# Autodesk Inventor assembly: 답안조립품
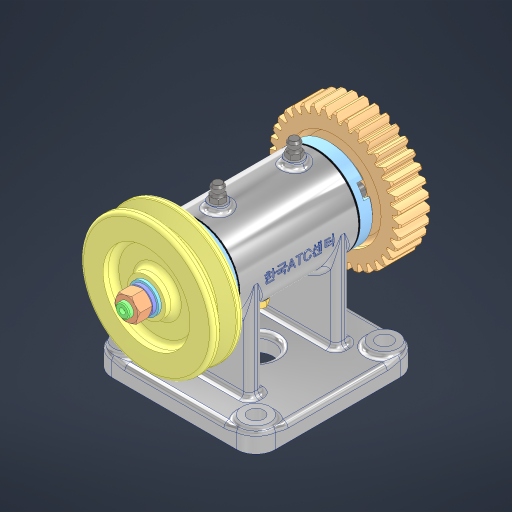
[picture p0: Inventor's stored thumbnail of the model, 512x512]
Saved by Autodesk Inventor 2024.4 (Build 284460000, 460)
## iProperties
Created: 2025-10
Part Number: 답안조립품
Document SubType Name: Assembly
Designer: user
Author: user
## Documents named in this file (24)
- C:\Users\user\Desktop\751003V1003\답안조립품.iam
- C:\Users\user\Desktop\751003V1003\본체.ipt
- C:\Users\user\Desktop\751003V1003\축\축\축.ipt
- C:\Users\user\Desktop\751003V1003\커버\커버\커버.ipt
- C:\Users\user\Desktop\751003V1003\커버\6각 구멍붙이 볼트 M4x10\6각 구멍붙이 볼트 M4x10.ipt
- C:\Users\user\Desktop\751003V1003\커버\6각 너트 M8x1\6각 너트 M8x1.ipt
- C:\Users\user\Desktop\751003V1003\커버\6각 머리 볼트 M6x0.75x8\6각 머리 볼트 M6x0.75x8.ipt
- C:\Users\user\Desktop\751003V1003\커버\V 벨트 풀리\V 벨트 풀리.ipt
- C:\Users\user\Desktop\751003V1003\커버\가스켓\가스켓.ipt
- C:\Users\user\Desktop\751003V1003\커버\그리스 니플 M6x0.75\그리스 니플 M6x0.75.ipt
- C:\Users\user\Desktop\751003V1003\커버\깊은 홈 볼 베어링 6002\깊은 홈 볼 베어링 6002.ipt
- C:\Users\user\Desktop\751003V1003\커버\스퍼 기어\스퍼 기어.ipt
- C:\Users\user\Desktop\751003V1003\커버\스프링 와셔 M8\스프링 와셔 M8.ipt
- C:\Users\user\Desktop\751003V1003\커버\실링\실링.ipt
- C:\Users\user\Desktop\751003V1003\커버\오일 실 15 25 4\오일 실 15 25 4.ipt
- C:\Users\user\Desktop\751003V1003\커버\평 와셔 M8\평 와셔 M8.ipt
- C:\Users\user\Desktop\751003V1003\커버\평행 키 3x3x12\평행 키 3x3x12.ipt
- C:\Users\user\Desktop\751003V1003\평행 키 3x3x12\평행 키 3x3x12\평행 키 3x3x12.ipt
- C:\Users\user\Desktop\751003V1003\커버\커버\커버_MIR.ipt
- C:\Users\user\Desktop\751003V1003\커버\가스켓\가스켓_MIR.ipt
- C:\Users\user\Desktop\751003V1003\커버\오일 실 15 25 4\오일 실 15 25 4_MIR.ipt
- C:\Users\user\Desktop\751003V1003\커버\6각 너트 M8x1\6각 너트 M8x1_MIR.ipt
- C:\Users\user\Desktop\751003V1003\커버\스프링 와셔 M8\스프링 와셔 M8_MIR.ipt
- C:\Users\user\Desktop\751003V1003\커버\평 와셔 M8\평 와셔 M8_MIR.ipt
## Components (15 placed, 8 different names)
1. 6각 너트 M8x1:1
2. 6각 머리 볼트 M6x0.75x8:1
3. V 벨트 풀리:1 — 각도:4
4. 가스켓:1
5. 그리스 니플 M6x0.75:1
6. 가스켓_MIR:1
7. 그리스 니플 M6x0.75:2
8. 6각 너트 M8x1_MIR:1
9. 6각 구멍붙이 볼트 M4x10:2
10. 6각 구멍붙이 볼트 M4x10:3
11. 6각 구멍붙이 볼트 M4x10:4
12. 6각 구멍붙이 볼트 M4x10:1
13. 6각 구멍붙이 볼트 M4x10:5
14. 6각 구멍붙이 볼트 M4x10:6
15. 6각 구멍붙이 볼트 M4x10:7
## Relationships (1: Angle 1)
- 각도:4 [Angle]: V 벨트 풀리:1
